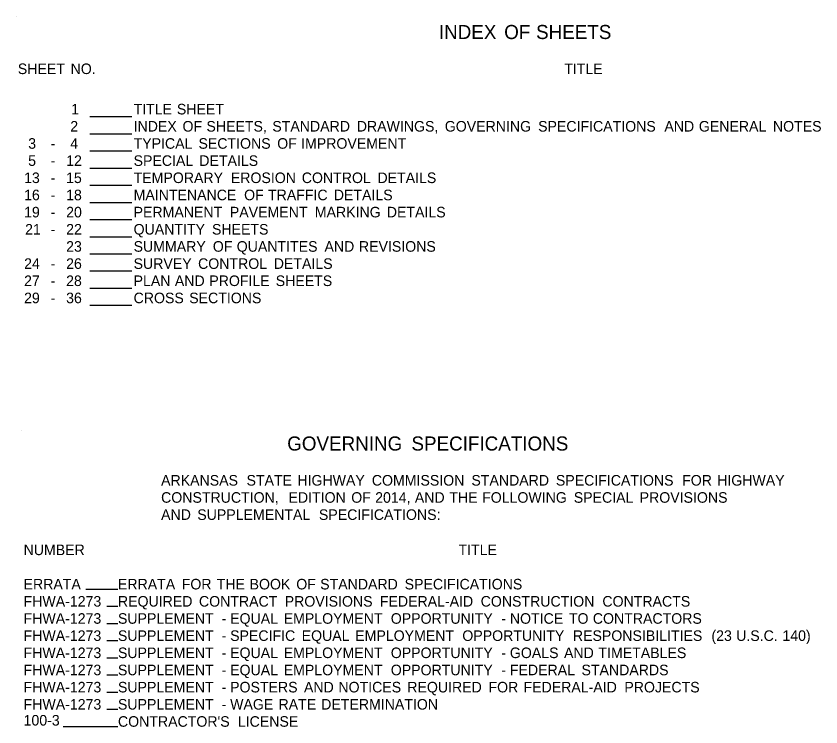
# Model space of a CAD drawing. Extents: x -1197 to 1681, y -1031 to 1021.
# Drawn here: x -1197 to -283, y 58 to 865 of the extents above; entities that cross this region are included whole.
import ezdxf

# ---------------------------------------------------------------- set-up
doc = ezdxf.new("R2010")
doc.units = 0
doc.layers.add('Default', color=7, linetype='Continuous')

msp = doc.modelspace()

# ---------------------------------------------------------------- linework, layer by layer
at = {"layer": 'Default'}
for p, q in [((-1197.49, 865.17), (-1197.49, 865.17)), ((-1113.64, 751.09), (-1065.86, 751.09)), ((-1113.64, 731.59), (-1065.86, 731.59)), ((-1113.64, 712.09), (-1065.86, 712.09)), ((-1113.64, 692.59), (-1065.86, 692.59)), ((-1113.64, 673.09), (-1065.86, 673.09)), ((-1113.64, 653.59), (-1065.86, 653.59)), ((-1113.64, 634.09), (-1065.86, 634.09)), ((-1113.64, 614.59), (-1065.86, 614.59)), ((-1113.64, 595.09), (-1065.86, 595.09)), ((-1113.64, 575.59), (-1065.86, 575.59)), ((-1113.64, 556.09), (-1065.86, 556.09)), ((-1113.64, 536.59), (-1065.86, 536.59)), ((-1190.9, 394.72), (-1190.9, 394.72)), ((-1081.7, 213.82), (-1118.31, 213.82)), ((-1081.7, 194.32), (-1094.38, 194.32)), ((-1081.7, 174.82), (-1094.38, 174.82)), ((-1081.7, 155.32), (-1094.38, 155.32)), ((-1081.7, 135.82), (-1094.38, 135.82)), ((-1081.7, 116.32), (-1094.38, 116.32)), ((-1081.7, 96.82), (-1094.38, 96.82)), ((-1081.7, 77.32), (-1094.38, 77.32)), ((-1081.7, 57.82), (-1143.97, 57.82))]:
    msp.add_line(p, q, dxfattribs=at)

# ---------------------------------------------------------------- texts
for s, height, p in [('INDEX', 16, (-716.91, 839.12)), (' OF', 16, (-648.6, 839.12)), (' SHEETS', 16, (-612.38, 839.12)), ('SHEET', 12, (-1195.54, 799.32)), (' NO.', 12, (-1139.97, 799.32)), ('TITLE', 12, (-574.42, 799.32)), ('1', 12, (-1134.79, 753.49)), ('TITLE', 12, (-1063.91, 753.49)), (' SHEET', 12, (-1019.16, 753.49)), ('2', 12, (-1135.89, 733.99)), ('INDEX', 12, (-1063.91, 733.99)), (' OF', 12, (-1012.77, 733.99)), (' SHEETS,', 12, (-985.6, 733.99)), (' STANDARD', 12, (-910.68, 733.99)), (' DRAWINGS,', 12, (-814.68, 733.99)), (' GOVERNING', 12, (-714.64, 733.99)), (' SPECIFICATIONS', 12, (-608.55, 733.99)), (' AND', 12, (-465.02, 733.99)), (' GENERAL', 12, (-425.85, 733.99)), (' NOTES', 12, (-341.65, 733.99)), ('3', 12, (-1183.73, 714.49)), ('4', 12, (-1135.93, 714.49)), ('TYPICAL', 12, (-1063.91, 714.49)), (' SECTIONS', 12, (-994.62, 714.49)), (' OF', 12, (-905.12, 714.49)), (' IMPROVEMENT', 12, (-877.95, 714.49)), ('-', 12, (-1158.09, 714.49)), ('5', 12, (-1183.77, 694.99)), ('12', 12, (-1140.55, 694.99)), ('SPECIAL', 12, (-1063.91, 694.99)), (' DETAILS', 12, (-993.68, 694.99)), ('-', 12, (-1158.09, 694.99)), ('13', 12, (-1188.39, 675.49)), ('15', 12, (-1140.66, 675.49)), ('TEMPORARY', 12, (-1063.91, 675.49)), (' EROSION', 12, (-957.82, 675.49)), (' CONTROL', 12, (-877.21, 675.49)), (' DETAILS', 12, (-791.17, 675.49)), ('-', 12, (-1158.09, 675.49)), ('16', 12, (-1188.39, 655.99)), ('18', 12, (-1140.62, 655.99)), ('MAINTENANCE', 12, (-1063.91, 655.99)), (' OF', 12, (-942.76, 655.99)), (' TRAFFIC', 12, (-915.58, 655.99)), (' DETAILS', 12, (-840.8, 655.99)), ('-', 12, (-1158.09, 655.99)), ('19', 12, (-1188.4, 636.49)), ('-', 12, (-1158.09, 636.49)), ('20', 12, (-1140.59, 636.49)), ('PERMANENT', 12, (-1063.91, 636.49)), (' PAVEMENT', 12, (-958.97, 636.49)), (' MARKING', 12, (-862.4, 636.49)), (' DETAILS', 12, (-780.54, 636.49)), ('21', 12, (-1187.23, 616.99)), ('-', 12, (-1158.09, 616.99)), ('22', 12, (-1140.55, 616.99)), ('QUANTITY', 12, (-1063.91, 616.99)), (' SHEETS', 12, (-979.26, 616.99)), ('23', 12, (-1140.61, 597.49)), ('SUMMARY', 12, (-1063.91, 597.49)), (' OF', 12, (-978.33, 597.49)), (' QUANTITES', 12, (-951.15, 597.49)), (' AND', 12, (-851.41, 597.49)), (' REVISIONS', 12, (-812.25, 597.49)), ('24', 12, (-1188.36, 577.99)), ('26', 12, (-1140.61, 577.99)), ('SURVEY', 12, (-1063.91, 577.99)), (' CONTROL', 12, (-995.08, 577.99)), (' DETAILS', 12, (-909.04, 577.99)), ('-', 12, (-1158.09, 577.99)), ('27', 12, (-1188.39, 558.49)), ('28', 12, (-1140.62, 558.49)), ('PLAN', 12, (-1063.91, 558.49)), (' AND', 12, (-1021.48, 558.49)), (' PROFILE', 12, (-982.32, 558.49)), (' SHEETS', 12, (-906.81, 558.49)), ('-', 12, (-1158.09, 558.49)), ('29', 12, (-1188.4, 538.99)), ('36', 12, (-1140.61, 538.99)), ('CROSS', 12, (-1063.91, 538.99)), (' SECTIONS', 12, (-1005.15, 538.99)), ('-', 12, (-1158.09, 538.99)), ('GOVERNING', 16, (-889.32, 371.6)), (' SPECIFICATIONS', 16, (-754.03, 371.6)), ('           ARKANSAS', 12, (-1081.7, 331.8)), (' STATE', 12, (-940.03, 331.8)), (' HIGHWAY', 12, (-882.22, 331.8)), (' COMMISSION', 12, (-797.58, 331.8)), (' STANDARD', 12, (-684.38, 331.8)), (' SPECIFICATIONS', 12, (-588.38, 331.8)), (' FOR', 12, (-444.85, 331.8)), (' HIGHWAY', 12, (-405.02, 331.8)), ('           CONSTRUCTION,', 12, (-1081.7, 312.3)), (' EDITION', 12, (-892.25, 312.3)), (' OF', 12, (-820.96, 312.3)), (' 2014,', 12, (-793.79, 312.3)), (' AND', 12, (-748.69, 312.3)), (' THE', 12, (-709.52, 312.3)), (' FOLLOWING', 12, (-672.22, 312.3)), (' SPECIAL', 12, (-568.02, 312.3)), (' PROVISIONS', 12, (-493.13, 312.3)), ('           AND', 12, (-1081.7, 292.8)), (' SUPPLEMENTAL', 12, (-995.98, 292.8)), (' SPECIFICATIONS:', 12, (-857.73, 292.8)), ('NUMBER', 12, (-1188.95, 252.82)), ('TITLE', 12, (-694.58, 252.82)), ('ERRATA', 12, (-1188.95, 213.82)), ('ERRATA', 12, (-1081.7, 213.82)), (' FOR', 12, (-1013.65, 213.82)), (' THE', 12, (-973.82, 213.82)), (' BOOK', 12, (-936.53, 213.82)), (' OF', 12, (-883.45, 213.82)), (' STANDARD', 12, (-856.28, 213.82)), (' SPECIFICATIONS', 12, (-760.28, 213.82)), ('FHWA-1273', 12, (-1188.95, 194.32)), ('REQUIRED', 12, (-1081.7, 194.32)), (' CONTRACT', 12, (-994.08, 194.32)), (' PROVISIONS', 12, (-896.61, 194.32)), (' FEDERAL-AID', 12, (-788.47, 194.32)), (' CONSTRUCTION', 12, (-673.84, 194.32)), (' CONTRACTS', 12, (-535.49, 194.32)), ('FHWA-1273', 12, (-1188.95, 174.82)), ('SUPPLEMENT', 12, (-1081.7, 174.82)), (' EQUAL', 12, (-958.64, 174.82)), (' EMPLOYMENT', 12, (-897.74, 174.82)), (' OPPORTUNITY', 12, (-776.03, 174.82)), (' NOTICE', 12, (-640.67, 174.82)), (' TO', 12, (-573.56, 174.82)), (' CONTRACTORS', 12, (-546.37, 174.82)), (' -', 12, (-968.36, 174.82)), (' -', 12, (-650.38, 174.82)), ('FHWA-1273', 12, (-1188.95, 155.32)), ('SUPPLEMENT', 12, (-1081.7, 155.32)), (' SPECIFIC', 12, (-958.64, 155.32)), (' EQUAL', 12, (-877.32, 155.32)), (' EMPLOYMENT', 12, (-816.42, 155.32)), (' OPPORTUNITY', 12, (-694.71, 155.32)), (' RESPONSIBILITIES', 12, (-569.06, 155.32)), (' (23', 12, (-411.54, 155.32)), (' U.S.C.', 12, (-383.42, 155.32)), (' 140)', 12, (-330.86, 155.32)), (' -', 12, (-968.36, 155.32)), ('FHWA-1273', 12, (-1188.95, 135.82)), ('SUPPLEMENT', 12, (-1081.7, 135.82)), (' EQUAL', 12, (-958.64, 135.82)), (' EMPLOYMENT', 12, (-897.74, 135.82)), (' OPPORTUNITY', 12, (-776.03, 135.82)), (' GOALS', 12, (-640.67, 135.82)), (' AND', 12, (-579.11, 135.82)), (' TIMETABLES', 12, (-539.95, 135.82)), (' -', 12, (-968.36, 135.82)), (' -', 12, (-650.38, 135.82)), ('FHWA-1273', 12, (-1188.95, 116.32)), ('SUPPLEMENT', 12, (-1081.7, 116.32)), (' EQUAL', 12, (-958.64, 116.32)), (' EMPLOYMENT', 12, (-897.74, 116.32)), (' OPPORTUNITY', 12, (-776.03, 116.32)), (' FEDERAL', 12, (-640.67, 116.32)), (' STANDARDS', 12, (-559.27, 116.32)), (' -', 12, (-968.36, 116.32)), (' -', 12, (-650.38, 116.32)), ('FHWA-1273', 12, (-1188.95, 96.82)), ('SUPPLEMENT', 12, (-1081.7, 96.82)), (' -', 12, (-968.36, 96.82)), (' POSTERS', 12, (-958.64, 96.82)), (' AND', 12, (-874.72, 96.82)), (' NOTICES', 12, (-835.56, 96.82)), (' REQUIRED', 12, (-757.25, 96.82)), (' FOR', 12, (-664.98, 96.82)), (' FEDERAL-AID', 12, (-625.16, 96.82)), (' PROJECTS', 12, (-510.53, 96.82)), ('FHWA-1273', 12, (-1188.95, 77.32)), ('SUPPLEMENT', 12, (-1081.7, 77.32)), (' -', 12, (-968.36, 77.32)), (' WAGE', 12, (-958.64, 77.32)), (' RATE', 12, (-903.65, 77.32)), (' DETERMINATION', 12, (-855.16, 77.32)), ('100-3', 12, (-1188.95, 59.17)), ("CONTRACTOR'S", 12, (-1081.7, 57.82)), (' LICENSE', 12, (-949.88, 57.82))]:
    msp.add_text(s, height=height, dxfattribs=at).set_placement(p)

doc.saveas('drawing.dxf')
